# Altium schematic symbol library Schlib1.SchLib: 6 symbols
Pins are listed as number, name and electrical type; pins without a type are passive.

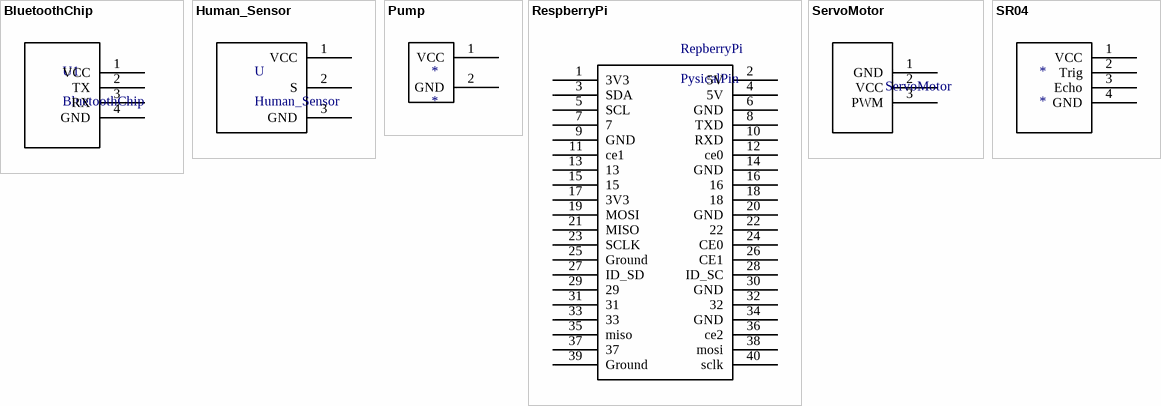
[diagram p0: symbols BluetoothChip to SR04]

## BluetoothChip
designator U1
pins: 1 VCC, 2 TX, 3 RX, 4 GND

## Human_Sensor
designator U
pins: 1 VCC, 2 S, 3 GND

## Pump
designator *
pins: 1 VCC, 2 GND

## RespberryPi
designator RepberryPi, comment PysicalPin
pins: 1 3V3, 2 5V, 3 SDA, 4 5V, 5 SCL, 6 GND, 7, 8 TXD, 9 GND, 10 RXD, 11 ce1, 12 ce0, 13, 14 GND, 15, 16, 17 3V3, 18, 19 MOSI, 20 GND, 21 MISO, 22, 23 SCLK, 24 CE0, 25 Ground, 26 CE1, 27 ID_SD, 28 ID_SC, 29, 30 GND, 31, 32, 33, 34 GND, 35 miso, 36 ce2, 37, 38 mosi, 39 Ground, 40 sclk

## ServoMotor
designator ServoMotor
pins: 1 GND, 2 VCC, 3 PWM

## SR04
designator *
pins: 1 VCC, 2 Trig, 3 Echo, 4 GND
